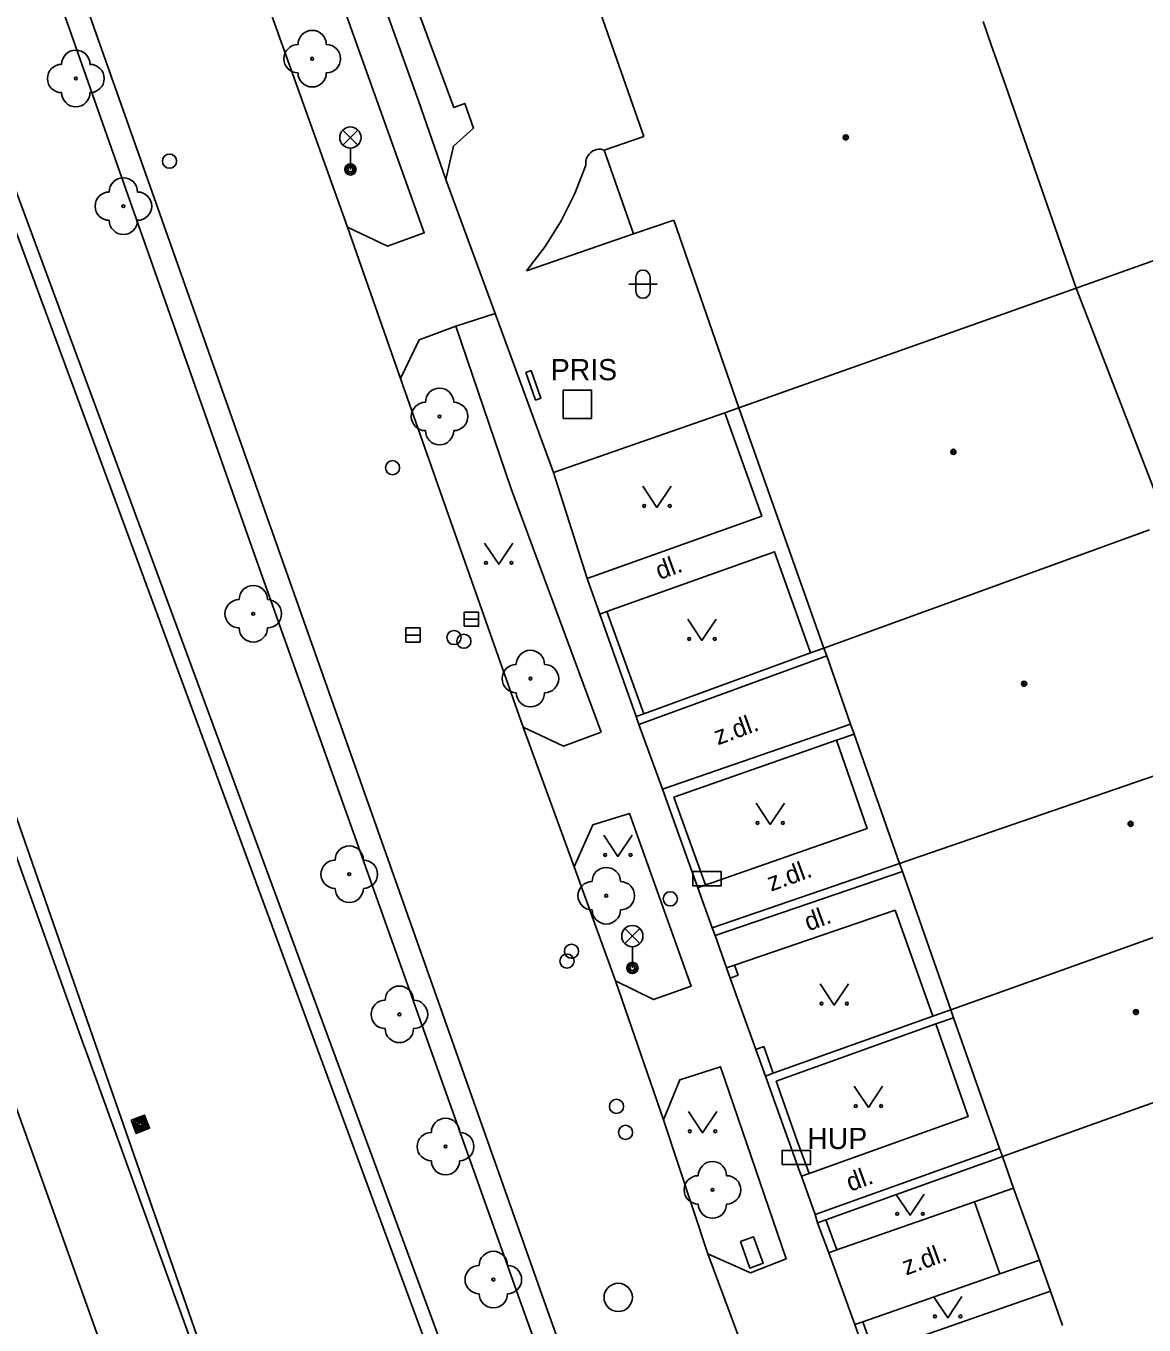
# Model space of a CAD drawing. Extents: x -596229 to -595156, y -1161237 to -1159376.
# Drawn here: x -596009.46 to -595969.96, y -1160841.16 to -1160795.27 of the extents above; entities that cross this region are included whole.
import ezdxf

# ---------------------------------------------------------------- set-up
doc = ezdxf.new("R2010")
doc.units = 0
for name, color, linetype in [('DOP - ploty', 7, 'Continuous'), ('Level 22', 7, 'Continuous'), ('Level 24', 7, 'Continuous'), ('Level 25', 7, 'Continuous'), ('Level 26', 7, 'Continuous'), ('Level 27', 7, 'Continuous'), ('Level 28', 7, 'Continuous'), ('Level 31', 7, 'Continuous'), ('Level 33', 7, 'Continuous'), ('Level 36', 7, 'Continuous'), ('Level 39', 7, 'Continuous'), ('silnoproud - povrch.  znaky a  RIS  skut. velikost', 7, 'Continuous'), ('Specificka linie pasportu komunikaci', 7, 'Continuous'), ('TM - budovy zdene_ betonove - VP', 7, 'Continuous'), ('TM - CD - osa koleji', 7, 'Continuous'), ('TM - chodniky - VP', 7, 'Continuous'), ('TM - horni hrana svahu', 7, 'Continuous'), ('TM - komunikace - VP', 7, 'Continuous'), ('TM - letecke snimky - pomocna linie', 7, 'Continuous'), ('TM - plot drateny_ kovovy - VP', 7, 'Continuous'), ('TM - podezdivka plotu - VP', 7, 'Continuous'), ('TM - popis objektu', 7, 'Continuous'), ('TM - popis povrchu', 7, 'Continuous'), ('TM - rozhrani ploch obecne - VP', 7, 'Continuous'), ('TM - vjezd na pozemek', 7, 'Continuous'), ('TM - zed operna - VP', 7, 'Continuous')]:
    doc.layers.add(name, color=color, linetype=linetype)

msp = doc.modelspace()

# ---------------------------------------------------------------- linework, layer by layer
at = {"layer": 'DOP - ploty'}
msp.add_lwpolyline([(-595972.36, -1160804.53), (-595969.02, -1160803.34)], dxfattribs=at)
at = {"layer": 'Level 22'}
for centre in [(-595999.35, -1160796.42), (-596007.7, -1160797.12), (-596006.02, -1160801.63), (-595994.85, -1160809.06), (-596001.43, -1160816.03), (-595991.64, -1160818.32), (-595998.04, -1160825.23), (-595988.96, -1160825.99), (-595996.27, -1160830.18), (-595994.64, -1160834.85), (-595985.21, -1160836.38), (-595992.95, -1160839.55)]:
    msp.add_circle(centre, 0.05, dxfattribs=at)
for centre, start, end in [((-595999.35, -1160795.92), 0, 180), ((-596007.7, -1160796.62), 0, 180), ((-595999.85, -1160796.42), 90, 270), ((-595998.85, -1160796.42), 270, 90), ((-596008.2, -1160797.12), 90, 270), ((-596007.2, -1160797.12), 270, 90), ((-595999.35, -1160796.92), 180, 0), ((-596007.7, -1160797.62), 180, 0), ((-596006.02, -1160801.13), 0, 180), ((-596006.52, -1160801.63), 90, 270), ((-596005.52, -1160801.63), 270, 90), ((-596006.02, -1160802.13), 180, 0), ((-595994.85, -1160808.56), 0, 180), ((-595995.35, -1160809.06), 90, 270), ((-595994.35, -1160809.06), 270, 90), ((-595994.85, -1160809.56), 180, 0), ((-596001.43, -1160815.53), 0, 180), ((-596001.93, -1160816.03), 90, 270), ((-596000.93, -1160816.03), 270, 90), ((-596001.43, -1160816.53), 180, 0), ((-595991.64, -1160817.82), 0, 180), ((-595992.14, -1160818.32), 90, 270), ((-595991.14, -1160818.32), 270, 90), ((-595991.64, -1160818.82), 180, 0), ((-595998.04, -1160824.73), 0, 180), ((-595998.54, -1160825.23), 90, 270), ((-595997.54, -1160825.23), 270, 90), ((-595988.96, -1160825.49), 0, 180), ((-595989.46, -1160825.99), 90, 270), ((-595988.46, -1160825.99), 270, 90), ((-595998.04, -1160825.73), 180, 0), ((-595988.96, -1160826.49), 180, 0), ((-595996.27, -1160829.68), 0, 180), ((-595996.77, -1160830.18), 90, 270), ((-595995.77, -1160830.18), 270, 90), ((-595996.27, -1160830.68), 180, 0), ((-595994.64, -1160834.35), 0, 180), ((-595995.14, -1160834.85), 90, 270), ((-595994.14, -1160834.85), 270, 90), ((-595994.64, -1160835.35), 180, 0), ((-595985.21, -1160835.88), 0, 180), ((-595985.71, -1160836.38), 90, 270), ((-595984.71, -1160836.38), 270, 90), ((-595985.21, -1160836.88), 180, 0), ((-595992.95, -1160839.05), 0, 180), ((-595993.45, -1160839.55), 90, 270), ((-595992.45, -1160839.55), 270, 90), ((-595992.95, -1160840.05), 180, 0)]:
    msp.add_arc(centre, 0.5, start, end, dxfattribs=at)
at = {"layer": 'Level 24'}
for points in [[(-595985.898, -1160825.639), (-595984.898, -1160825.639), (-595984.898, -1160825.139), (-595985.898, -1160825.139)], [(-595982.748, -1160835.489), (-595981.748, -1160835.489), (-595981.748, -1160834.989), (-595982.748, -1160834.989)], [(-595984.225, -1160838.205), (-595983.885, -1160839.145), (-595983.415, -1160838.975), (-595983.755, -1160838.035)]]:
    msp.add_lwpolyline(points, close=True, dxfattribs=at)
at = {"layer": 'Level 25'}
for points in [[(-596005.744, -1160833.918), (-596005.562, -1160834.384), (-596005.096, -1160834.202), (-596005.278, -1160833.736)], [(-596005.679, -1160833.946), (-596005.534, -1160834.319), (-596005.161, -1160834.174), (-596005.306, -1160833.801)], [(-596005.614, -1160833.975), (-596005.505, -1160834.254), (-596005.226, -1160834.145), (-596005.335, -1160833.866)], [(-596005.549, -1160834.003), (-596005.477, -1160834.189), (-596005.291, -1160834.117), (-596005.363, -1160833.931)], [(-596005.485, -1160834.032), (-596005.448, -1160834.125), (-596005.355, -1160834.088), (-596005.392, -1160833.995)]]:
    msp.add_lwpolyline(points, close=True, dxfattribs=at)
at = {"layer": 'Level 26'}
msp.add_lwpolyline([(-595990.48, -1160809.13), (-595989.48, -1160809.13), (-595989.48, -1160808.13), (-595990.48, -1160808.13)], close=True, dxfattribs=at)
at = {"layer": 'Level 27'}
for p, q in [((-595993.98, -1160816.22), (-595993.48, -1160816.22)), ((-595996.04, -1160816.78), (-595995.54, -1160816.78))]:
    msp.add_line(p, q, dxfattribs=at)
for points in [[(-595993.98, -1160816.47), (-595993.48, -1160816.47), (-595993.48, -1160815.97), (-595993.98, -1160815.97)], [(-595996.04, -1160817.03), (-595995.54, -1160817.03), (-595995.54, -1160816.53), (-595996.04, -1160816.53)]]:
    msp.add_lwpolyline(points, close=True, dxfattribs=at)
msp.add_circle((-595988.54, -1160840.18), 0.5, dxfattribs=at)
at = {"layer": 'Level 28'}
for centre in [(-596004.39, -1160800.04), (-595996.51, -1160810.87), (-595994.34, -1160816.87), (-595993.99, -1160817), (-595990.19, -1160827.95), (-595990.35, -1160828.3), (-595988.6, -1160833.43), (-595988.28, -1160834.35)]:
    msp.add_circle(centre, 0.25, dxfattribs=at)
at = {"layer": 'Level 31'}
msp.add_circle((-595986.7, -1160826.1), 0.25, dxfattribs=at)
at = {"layer": 'Level 33'}
for p, q in [((-595998.265, -1160799.47), (-595997.735, -1160798.94)), ((-595998.265, -1160798.94), (-595997.735, -1160799.47)), ((-595998, -1160799.58), (-595998, -1160800.33)), ((-595988.305, -1160827.68), (-595987.775, -1160827.15)), ((-595988.305, -1160827.15), (-595987.775, -1160827.68)), ((-595988.04, -1160827.79), (-595988.04, -1160828.54))]:
    msp.add_line(p, q, dxfattribs=at)
for centre, radius in [((-595998, -1160799.205), 0.375), ((-595998, -1160800.33), 0.2), ((-595998, -1160800.33), 0.145), ((-595998, -1160800.33), 0.0876), ((-595988.04, -1160827.415), 0.375), ((-595988.04, -1160828.54), 0.2), ((-595988.04, -1160828.54), 0.145), ((-595988.04, -1160828.54), 0.0876)]:
    msp.add_circle(centre, radius, dxfattribs=at)
at = {"layer": 'Level 36'}
for p, q in [((-595988.166, -1160804.386), (-595987.166, -1160804.386)), ((-595987.916, -1160804.136), (-595987.916, -1160804.636)), ((-595987.416, -1160804.136), (-595987.416, -1160804.636))]:
    msp.add_line(p, q, dxfattribs=at)
for points in [[(-595987.67, -1160811.52), (-595987.17, -1160812.27), (-595986.67, -1160811.52)], [(-595993.26, -1160813.53), (-595992.76, -1160814.28), (-595992.26, -1160813.53)], [(-595986.08, -1160816.22), (-595985.58, -1160816.97), (-595985.08, -1160816.22)], [(-595983.67, -1160822.72), (-595983.17, -1160823.47), (-595982.67, -1160822.72)], [(-595989.05, -1160823.85), (-595988.55, -1160824.6), (-595988.05, -1160823.85)], [(-595981.41, -1160829.1), (-595980.91, -1160829.85), (-595980.41, -1160829.1)], [(-595980.2, -1160832.72), (-595979.7, -1160833.47), (-595979.2, -1160832.72)], [(-595986.06, -1160833.61), (-595985.56, -1160834.36), (-595985.06, -1160833.61)], [(-595978.73, -1160836.53), (-595978.23, -1160837.28), (-595977.73, -1160836.53)], [(-595977.4, -1160840.15), (-595976.9, -1160840.9), (-595976.4, -1160840.15)]]:
    msp.add_lwpolyline(points, dxfattribs=at)
for centre in [(-595987.62, -1160812.22), (-595986.721, -1160812.22), (-595993.21, -1160814.23), (-595992.311, -1160814.23), (-595986.03, -1160816.92), (-595985.131, -1160816.92), (-595983.62, -1160823.42), (-595982.721, -1160823.42), (-595989, -1160824.55), (-595988.101, -1160824.55), (-595981.36, -1160829.8), (-595980.461, -1160829.8), (-595980.15, -1160833.42), (-595979.251, -1160833.42), (-595986.01, -1160834.31), (-595985.111, -1160834.31), (-595978.68, -1160837.23), (-595977.781, -1160837.23), (-595977.35, -1160840.85), (-595976.451, -1160840.85)]:
    msp.add_circle(centre, 0.05, dxfattribs=at)
for centre, start, end in [((-595987.666, -1160804.136), 0, 180), ((-595987.666, -1160804.636), 180, 0)]:
    msp.add_arc(centre, 0.25, start, end, dxfattribs=at)
at = {"layer": 'Level 39'}
for centre, radius in [((-595980.5, -1160799.2), 0.09), ((-595980.5, -1160799.2), 0.0398), ((-595976.7, -1160810.31), 0.09), ((-595976.7, -1160810.31), 0.0398), ((-595974.2, -1160818.5), 0.09), ((-595974.2, -1160818.5), 0.0398), ((-595970.44, -1160823.45), 0.09), ((-595970.44, -1160823.45), 0.0398), ((-595970.25, -1160830.1), 0.09), ((-595970.25, -1160830.1), 0.0398)]:
    msp.add_circle(centre, radius, dxfattribs=at)
at = {"layer": 'silnoproud - povrch.  znaky a  RIS  skut. velikost'}
msp.add_lwpolyline([(-595991.61, -1160807.44), (-595991.27, -1160808.41), (-595991.46, -1160808.48), (-595991.8, -1160807.51), (-595991.61, -1160807.44)], dxfattribs=at)
at = {"layer": 'Specificka linie pasportu komunikaci'}
for points in [[(-595994.27, -1160805.87), (-595992.89, -1160805.42)], [(-595987.63, -1160819.56), (-595988.94, -1160815.95)]]:
    msp.add_lwpolyline(points, dxfattribs=at)
at = {"layer": 'TM - budovy zdene_ betonove - VP'}
for points in [[(-595987.64, -1160799.17), (-595989.95, -1160792.54)], [(-595975.65, -1160795.11), (-595975.36, -1160795.93)], [(-595974.86, -1160797.36), (-595975.36, -1160795.93)], [(-595974.86, -1160797.36), (-595972.36, -1160804.53)], [(-595989.03, -1160799.65), (-595987.64, -1160799.17)], [(-595988, -1160802.61), (-595989.03, -1160799.65)], [(-595986.57, -1160802.12), (-595988, -1160802.61)], [(-595984.28, -1160808.76), (-595986.57, -1160802.12)], [(-595984.28, -1160808.76), (-595972.36, -1160804.53)], [(-595972.36, -1160804.53), (-595969.15, -1160812.84)], [(-595981.27, -1160817.24), (-595984.28, -1160808.76)], [(-595981.27, -1160817.24), (-595969.77, -1160813.06)], [(-595981.17, -1160817.52), (-595981.27, -1160817.24)], [(-595980.33, -1160819.93), (-595981.17, -1160817.52)], [(-595980.2, -1160820.28), (-595980.33, -1160819.93)], [(-595978.6, -1160824.85), (-595980.2, -1160820.28)], [(-595978.6, -1160824.85), (-595967.38, -1160820.99)], [(-595978.5, -1160825.13), (-595978.6, -1160824.85)], [(-595976.79, -1160830.02), (-595978.5, -1160825.13)], [(-595966.44, -1160826.32), (-595976.79, -1160830.02)], [(-595976.69, -1160830.3), (-595976.79, -1160830.02)], [(-595975.07, -1160834.92), (-595976.69, -1160830.3)], [(-595963.82, -1160831.22), (-595974.97, -1160835.2)], [(-595974.97, -1160835.2), (-595975.07, -1160834.92)], [(-595974.57, -1160836.32), (-595974.97, -1160835.2)], [(-595973.66, -1160838.86), (-595974.57, -1160836.32)], [(-595973.27, -1160839.96), (-595973.66, -1160838.86)], [(-595972.84, -1160841.17), (-595973.27, -1160839.96)]]:
    msp.add_lwpolyline(points, dxfattribs=at)
at = {"layer": 'TM - CD - osa koleji'}
msp.add_lwpolyline([(-595990.55, -1160887.41), (-595998.47, -1160865.23), (-596009.21, -1160835.14), (-596012.3, -1160826.56), (-596021.76, -1160799.99), (-596036.31, -1160759.24)], dxfattribs=at)
at = {"layer": 'TM - chodniky - VP'}
for points in [[(-596000.39, -1160788.59), (-595995.39, -1160802.57), (-595996.69, -1160803.04), (-595998.1, -1160802.37)], [(-596001.42, -1160813.84), (-596009.34, -1160791.35)], [(-595996.23, -1160807.72), (-595995.57, -1160806.35), (-595994.27, -1160805.87)], [(-595994.27, -1160805.87), (-595992.32, -1160811.62), (-595989.14, -1160820.21)], [(-595989.64, -1160814.78), (-595983.47, -1160812.58), (-595984.77, -1160808.93)], [(-595991.95, -1160840.44), (-596001.42, -1160813.84)], [(-595988.94, -1160815.95), (-595983.02, -1160813.84), (-595981.75, -1160817.41)], [(-595989.19, -1160816.04), (-595988.94, -1160815.95)], [(-595989.14, -1160820.21), (-595990.47, -1160820.71), (-595991.9, -1160820.03)], [(-595985.45, -1160825.61), (-595985.23, -1160825.53), (-595979.75, -1160823.62), (-595980.83, -1160820.5)], [(-595990.1, -1160824.97), (-595989.44, -1160823.48), (-595988.14, -1160823.08), (-595985.96, -1160829.19), (-595987.29, -1160829.66), (-595988.63, -1160829)], [(-595978.75, -1160826.5), (-595984.43, -1160828.44)], [(-595977.42, -1160830.24), (-595978.75, -1160826.5)], [(-595981.79, -1160835.8), (-595976.18, -1160833.79), (-595977.32, -1160830.52)], [(-595986.94, -1160833.91), (-595986.36, -1160832.49), (-595984.93, -1160832.03), (-595982.61, -1160838.82), (-595983.87, -1160839.31), (-595985.37, -1160838.64)], [(-595975.95, -1160836.8), (-595974.57, -1160836.32)], [(-595980.82, -1160838.5), (-595975.95, -1160836.8)], [(-595975.06, -1160839.35), (-595973.66, -1160838.86)], [(-595979.9, -1160841.04), (-595975.06, -1160839.35)], [(-595979.51, -1160842.14), (-595973.27, -1160839.96)], [(-595986.83, -1160854.67), (-595991.95, -1160840.44)]]:
    msp.add_lwpolyline(points, dxfattribs=at)
at = {"layer": 'TM - horni hrana svahu'}
msp.add_lwpolyline([(-595996.62, -1160861.07), (-596017.15, -1160802.12), (-596030.65, -1160763.51)], dxfattribs=at)
at = {"layer": 'TM - komunikace - VP'}
for points in [[(-596002.73, -1160789.43), (-595998.1, -1160802.37)], [(-596008.57, -1160791.03), (-596000.61, -1160813.56)], [(-595998.1, -1160802.37), (-595996.23, -1160807.72)], [(-595996.23, -1160807.72), (-595994.68, -1160812.15), (-595991.9, -1160820.03)], [(-596000.61, -1160813.56), (-595991.22, -1160840.11)], [(-595991.9, -1160820.03), (-595990.1, -1160824.97)], [(-595990.1, -1160824.97), (-595988.63, -1160829)], [(-595988.63, -1160829), (-595986.94, -1160833.91)], [(-595986.94, -1160833.91), (-595985.37, -1160838.64)], [(-595985.37, -1160838.64), (-595983.49, -1160843.7)], [(-595991.22, -1160840.11), (-595986.18, -1160854.27)]]:
    msp.add_lwpolyline(points, dxfattribs=at)
at = {"layer": 'TM - letecke snimky - pomocna linie'}
for points in [[(-595996.62, -1160861.07), (-596007.32, -1160831.53), (-596007.46, -1160831.15), (-596009.47, -1160825.55), (-596018.93, -1160798.98), (-596020.72, -1160793.98), (-596020.99, -1160793.22), (-596033.48, -1160758.23), (-596033.98, -1160756.85), (-596034.14, -1160756.41), (-596047.11, -1160720.07), (-596047.28, -1160719.6), (-596061.54, -1160680.38)], [(-595994.63, -1160800.69), (-595994.36, -1160799.51), (-595993.65, -1160798.87), (-595993.96, -1160798), (-595994.35, -1160798.14), (-595996, -1160793.68), (-595991.53, -1160792.03)], [(-595989.68, -1160800.18), (-595989.68, -1160800.05), (-595989.67, -1160799.97), (-595989.64, -1160799.89), (-595989.57, -1160799.79), (-595989.51, -1160799.73), (-595989.44, -1160799.68), (-595989.37, -1160799.65), (-595989.31, -1160799.63), (-595989.24, -1160799.62), (-595989.15, -1160799.62), (-595989.03, -1160799.65)], [(-595991.78, -1160803.91), (-595991.12, -1160803.06), (-595990.55, -1160802.15), (-595990.07, -1160801.18), (-595989.68, -1160800.18)], [(-595988, -1160802.61), (-595991.78, -1160803.91)], [(-595975.95, -1160836.8), (-595975.06, -1160839.35)]]:
    msp.add_lwpolyline(points, dxfattribs=at)
at = {"layer": 'TM - plot drateny_ kovovy - VP'}
for points in [[(-595999.13, -1160788.06), (-595995.59, -1160797.91)], [(-595994.63, -1160800.69), (-595995.59, -1160797.91)], [(-595992.89, -1160805.42), (-595994.63, -1160800.69)], [(-595990.82, -1160811.04), (-595992.89, -1160805.42)], [(-595990.82, -1160811.04), (-595984.77, -1160808.93)], [(-595984.77, -1160808.93), (-595984.28, -1160808.76)], [(-595989.64, -1160814.78), (-595990.82, -1160811.04)], [(-595987.91, -1160819.66), (-595989.19, -1160816.04)], [(-595987.81, -1160819.94), (-595981.17, -1160817.52)], [(-595986.57, -1160822.51), (-595980.83, -1160820.5)], [(-595980.83, -1160820.5), (-595980.2, -1160820.28)], [(-595985.45, -1160825.61), (-595985.58, -1160825.25), (-595986.57, -1160822.51)], [(-595985.12, -1160827.4), (-595978.5, -1160825.13)], [(-595984.3, -1160828.8), (-595984.43, -1160828.44)], [(-595982.96, -1160832.54), (-595977.32, -1160830.52)], [(-595977.32, -1160830.52), (-595976.69, -1160830.3)], [(-595983.06, -1160832.26), (-595983.4, -1160831.32)], [(-595982.2, -1160834.68), (-595982.96, -1160832.54)], [(-595982.2, -1160834.68), (-595981.79, -1160835.8)], [(-595975.07, -1160834.92), (-595981.58, -1160837.25)], [(-595980.82, -1160838.5), (-595981.2, -1160837.44)], [(-595979.51, -1160842.14), (-595979.9, -1160841.04)]]:
    msp.add_lwpolyline(points, dxfattribs=at)
at = {"layer": 'TM - podezdivka plotu - VP'}
for points in [[(-595981.75, -1160817.41), (-595981.27, -1160817.24)], [(-595987.63, -1160819.56), (-595981.75, -1160817.41)], [(-595987.91, -1160819.66), (-595987.63, -1160819.56)], [(-595987.81, -1160819.94), (-595987.91, -1160819.66)], [(-595980.33, -1160819.93), (-595986.98, -1160822.23)], [(-595985.73, -1160825.71), (-595986.98, -1160822.23)], [(-595985.22, -1160827.12), (-595978.6, -1160824.85)], [(-595985.73, -1160825.71), (-595985.45, -1160825.61)], [(-595985.12, -1160827.4), (-595985.22, -1160827.12)], [(-595984.71, -1160828.54), (-595984.43, -1160828.44)], [(-595984.58, -1160828.9), (-595984.71, -1160828.54)], [(-595984.3, -1160828.8), (-595984.58, -1160828.9)], [(-595976.79, -1160830.02), (-595977.42, -1160830.24)], [(-595977.42, -1160830.24), (-595983.06, -1160832.26)], [(-595983.4, -1160831.32), (-595983.68, -1160831.42)], [(-595983.34, -1160832.36), (-595983.68, -1160831.42)], [(-595983.06, -1160832.26), (-595983.34, -1160832.36)], [(-595982.13, -1160835.72), (-595983.34, -1160832.36)], [(-595974.97, -1160835.2), (-595981.2, -1160837.44)], [(-595982.07, -1160835.9), (-595982.13, -1160835.72)], [(-595981.79, -1160835.8), (-595982.07, -1160835.9)], [(-595981.5, -1160837.55), (-595981.58, -1160837.25)], [(-595981.2, -1160837.44), (-595981.5, -1160837.55)], [(-595981.1, -1160838.6), (-595981.5, -1160837.55)], [(-595980.82, -1160838.5), (-595981.1, -1160838.6)], [(-595979.9, -1160841.04), (-595980.18, -1160841.14)], [(-595979.79, -1160842.24), (-595980.18, -1160841.14)]]:
    msp.add_lwpolyline(points, dxfattribs=at)
at = {"layer": 'TM - rozhrani ploch obecne - VP'}
msp.add_lwpolyline([(-595980.7, -1160881.58), (-595983.63, -1160873.7), (-595995.28, -1160841.96), (-596005.54, -1160814.09), (-596013.99, -1160791.24)], dxfattribs=at)
at = {"layer": 'TM - vjezd na pozemek'}
for points in [[(-595989.64, -1160814.78), (-595989.19, -1160816.04)], [(-595987.81, -1160819.94), (-595986.98, -1160822.23)], [(-595985.73, -1160825.71), (-595985.22, -1160827.12)], [(-595985.12, -1160827.4), (-595984.71, -1160828.54)], [(-595984.58, -1160828.9), (-595983.68, -1160831.42)], [(-595982.07, -1160835.9), (-595981.58, -1160837.25)], [(-595981.1, -1160838.6), (-595980.18, -1160841.14)]]:
    msp.add_lwpolyline(points, dxfattribs=at)
at = {"layer": 'TM - zed operna - VP'}
msp.add_lwpolyline([(-595989.83, -1160855.02), (-595994.81, -1160841.79), (-596005.07, -1160813.92), (-596012.89, -1160792.77)], dxfattribs=at)

# ---------------------------------------------------------------- texts
at = {"layer": 'TM - popis objektu'}
for s, p in [('PRIS', (-595990.92, -1160807.78)), ('HUP', (-595981.86, -1160834.94))]:
    msp.add_text(s, height=0.75, dxfattribs=at).set_placement(p)
at = {"layer": 'TM - popis povrchu'}
for s, p in [('dl.', (-595987.08, -1160814.84)), ('z.dl.', (-595985.02, -1160820.68)), ('z.dl.', (-595983.14, -1160825.85)), ('dl.', (-595981.82, -1160827.25)), ('dl.', (-595980.34, -1160836.45)), ('z.dl.', (-595978.37, -1160839.41))]:
    msp.add_text(s, height=0.65, rotation=20.05, dxfattribs=at).set_placement(p)

doc.saveas('drawing.dxf')
